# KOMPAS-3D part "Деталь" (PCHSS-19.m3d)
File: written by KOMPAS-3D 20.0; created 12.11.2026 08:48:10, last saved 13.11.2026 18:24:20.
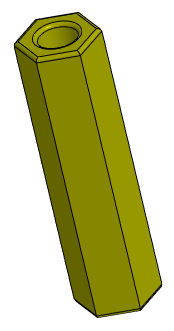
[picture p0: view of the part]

Document properties: Полное имя файла: D:\myProjects\Progect_esp32\box_compas\прочее\PCHSS-19.m3d

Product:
- Part/product: Деталь
    Масса: 0.0019975

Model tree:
1. Эскиз:1
2. Элемент выдавливания:1
     Расстояние 1 = 19
3. Эскиз:2  (with: Элемент выдавливания:1)
4. Элемент выдавливания:2
     Расстояние 2 = 19
5. Скругление:1  (with: Элемент выдавливания:1)
     Радиус = 0.25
